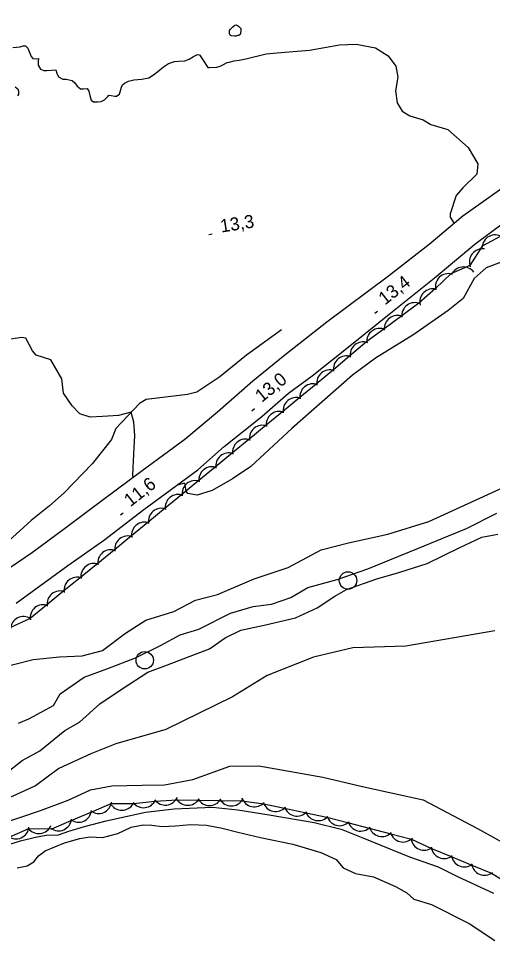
# Model space of a CAD drawing. Extents: x 643342 to 646936, y 5873857 to 5876103.
# Drawn here: x 645260 to 645368.8, y 5874232.4 to 5874444 of the extents above; entities that cross this region are included whole.
import ezdxf

# ---------------------------------------------------------------- set-up
doc = ezdxf.new("R2010")
doc.units = 0
for name, color, linetype in [('Niveau 1', 7, 'Continuous'), ('Niveau 2', 7, 'Continuous'), ('Niveau 21', 7, 'Continuous'), ('Niveau 22', 7, 'Continuous'), ('Niveau 3', 7, 'Continuous'), ('Niveau 36', 7, 'Continuous'), ('Niveau 4', 7, 'Continuous'), ('Niveau 44', 7, 'Continuous')]:
    doc.layers.add(name, color=color, linetype=linetype)

msp = doc.modelspace()

# ---------------------------------------------------------------- linework, layer by layer
at = {"layer": 'Niveau 1'}
msp.add_lwpolyline([(645242.67, 5874298.35), (645244.98, 5874297.7), (645249.37, 5874295.72), (645253.54, 5874295.31), (645258.53, 5874295.66), (645263.34, 5874296.94), (645269.42, 5874297.54), (645274.59, 5874297.73), (645279.29, 5874298.94), (645284.56, 5874302.93), (645289.25, 5874305.9), (645295.64, 5874307.93), (645300.65, 5874310.5), (645305.68, 5874311.85), (645314.06, 5874315.42), (645321.92, 5874318.02), (645329.45, 5874322.05), (645335.75, 5874323.66), (645344.8, 5874325.7), (645354.15, 5874328.58), (645372.21, 5874336.86)], dxfattribs=at)
at = {"layer": 'Niveau 2'}
for points in [[(645309.16, 5874442.08), (645309.61, 5874442.46), (645309.95, 5874442.53), (645310.25, 5874442.41), (645310.51, 5874442.24), (645311.04, 5874441.7), (645311.06, 5874441.36), (645310.98, 5874440.57), (645310.81, 5874440.32), (645310.58, 5874440.1), (645310.25, 5874440.08), (645309.92, 5874439.95), (645309.58, 5874439.93), (645308.8, 5874440.01), (645308.54, 5874440.18), (645308.42, 5874440.46), (645308.39, 5874440.8), (645308.45, 5874441.24), (645308.62, 5874441.5), (645309.16, 5874442.08)], [(645258.69, 5874437.32), (645260.38, 5874437.46), (645261.04, 5874437.71), (645261.62, 5874437.71), (645262.1, 5874437.16), (645262.89, 5874435.23)], [(645283.15, 5874426.65), (645283.65, 5874428.24), (645283.9, 5874428.8), (645284.3, 5874429.17), (645285.24, 5874429.59), (645286.48, 5874429.89), (645287.35, 5874429.96), (645288.27, 5874430.03), (645289.94, 5874430.36), (645291, 5874431.08), (645292.01, 5874431.79), (645293.24, 5874432.87), (645294.39, 5874433.64), (645295.76, 5874434.09), (645296.78, 5874434.17), (645298.18, 5874434.29), (645299.17, 5874434.66), (645300.19, 5874435.28), (645301.08, 5874435.69), (645301.52, 5874435.63), (645302.42, 5874434.24), (645303.46, 5874432.77), (645303.75, 5874432.74), (645305.5, 5874432.79), (645306.31, 5874433.05), (645306.92, 5874433.34), (645307.89, 5874433.9), (645308.37, 5874433.94), (645309.46, 5874434.27), (645310.67, 5874434.42), (645312.15, 5874434.74), (645316.83, 5874435.84), (645319.33, 5874436.14), (645322.14, 5874436.32), (645326.8, 5874436.75)], [(645326.8, 5874436.75), (645333.69, 5874437.93), (645337.5, 5874438.13), (645341.91, 5874437.27), (645344.82, 5874435.45), (645346.58, 5874433.03), (645347.07, 5874430.49), (645346.52, 5874427.36), (645346.91, 5874424.64), (645348.08, 5874422.74), (645349.83, 5874421.66), (645352.91, 5874420.74), (645354.61, 5874419.66), (645358.54, 5874418.5), (645363.17, 5874414.38), (645365.44, 5874410.65), (645365.2, 5874408.3), (645361.99, 5874405.1), (645360.42, 5874403.36), (645359.07, 5874399.18), (645359.07, 5874398.37), (645359.99, 5874396.98)], [(645262.89, 5874435.23), (645263.27, 5874434.82), (645264.15, 5874434.75), (645264.58, 5874434.78), (645264.49, 5874434.09), (645264.51, 5874433.27), (645265.07, 5874432.39), (645265.78, 5874432.06), (645266.46, 5874432.06), (645268.54, 5874432.18), (645268.8, 5874431.42), (645269.21, 5874430.58), (645270.13, 5874430.07), (645270.91, 5874430.04), (645272.34, 5874429.72), (645272.92, 5874429.23), (645273.42, 5874428.49), (645274.24, 5874427.87), (645274.93, 5874427.88), (645275.79, 5874427.95), (645276.14, 5874427.34), (645276.37, 5874426.29), (645276.7, 5874425.25), (645277.21, 5874424.9), (645278.19, 5874424.88), (645278.96, 5874424.94), (645279.75, 5874425.35), (645280.47, 5874426.09), (645280.69, 5874426.4), (645281.23, 5874426.35), (645282.12, 5874426.13), (645282.46, 5874426.15), (645282.78, 5874426.37), (645283.15, 5874426.65)], [(645259.84, 5874426.22), (645260.1, 5874426.63), (645260.05, 5874427.21), (645260.02, 5874427.6), (645259.19, 5874428.21)], [(645371.37, 5874388.34), (645367.35, 5874386.78), (645364.61, 5874384.31), (645362.06, 5874379.75), (645358.59, 5874377), (645350.76, 5874371.49), (645341.95, 5874366.02), (645336.63, 5874362.15), (645322.74, 5874349.9), (645313.32, 5874341.18), (645309.09, 5874338.38), (645304.44, 5874335.71), (645300.97, 5874334.6), (645298.85, 5874334.97), (645298.46, 5874335.53), (645298.17, 5874337.38), (645296.38, 5874336.92)], [(645286.29, 5874338.62), (645286.21, 5874339.12), (645286.33, 5874340.88), (645286.54, 5874345.45), (645286.7, 5874348.33), (645286.44, 5874351.35), (645285.86, 5874353.67), (645282.95, 5874352.88), (645279.3, 5874352.63), (645276.43, 5874352.48), (645274.1, 5874353.29), (645272.29, 5874355.09), (645270.35, 5874358.05), (645269.96, 5874361.3), (645267.45, 5874365.63), (645264.06, 5874366.71), (645263.2, 5874367.76), (645261.67, 5874370.64), (645260.79, 5874370.81), (645256.72, 5874370.18)], [(645260.02, 5874282.28), (645262.36, 5874283.26), (645267.99, 5874286.35), (645269.56, 5874289.04), (645275.08, 5874292.83), (645280.49, 5874294.85), (645286.86, 5874297.29), (645292.62, 5874300.1), (645297.12, 5874302.58), (645301.41, 5874303.88), (645308.63, 5874307.55), (645313.89, 5874309.09), (645318.05, 5874309.62), (645322.5, 5874311.1), (645326.37, 5874313.42), (645333.13, 5874315.24), (645340.19, 5874317.73), (645345.24, 5874319.78), (645351.82, 5874322.47), (645358.68, 5874325.29), (645362.82, 5874326.93), (645369.8, 5874330.52)], [(645289.68, 5874294.04), (645294.18, 5874295.7), (645300.39, 5874298.08), (645303.81, 5874299.37), (645307.44, 5874301.86), (645311.06, 5874303.64), (645316.35, 5874304.77), (645323.6, 5874306.45), (645328.58, 5874308.74), (645332.61, 5874311.43), (645335.25, 5874312.96), (645342.26, 5874315.45), (645347.3, 5874316.86), (645353.76, 5874318.95), (645361.16, 5874322.52), (645366.36, 5874325), (645370.05, 5874325.67)], [(645369.34, 5874303.51), (645348.89, 5874299.96), (645336.76, 5874299.58), (645327.67, 5874297.41), (645317.07, 5874293.26), (645309.1, 5874288.35), (645293.81, 5874280.81), (645282.32, 5874277.53), (645276.62, 5874275.25), (645269.24, 5874271.91), (645263.89, 5874267.89), (645253.43, 5874263.15), (645241.62, 5874259.5), (645234.18, 5874256.85), (645222.41, 5874252.49), (645212.69, 5874250.51), (645204.39, 5874248.52), (645199.45, 5874246.11)], [(645211.19, 5874263.91), (645214.93, 5874261.36), (645218.67, 5874260.57), (645226.45, 5874261.47), (645233.78, 5874262.11), (645241.81, 5874264.43), (645247.71, 5874265.44), (645255.38, 5874269.5), (645260.83, 5874273.76), (645264.89, 5874275.92), (645270.65, 5874280.61), (645273.97, 5874282.55), (645278.66, 5874286.75), (645283.8, 5874290.16), (645289.68, 5874294.04)], [(645255.49, 5874259.08), (645265.02, 5874262.23), (645271.36, 5874264.62), (645276.54, 5874266.99), (645281.4, 5874267.92), (645288.36, 5874268.06), (645293.51, 5874268.19), (645299.99, 5874269.41), (645308.52, 5874272.42), (645315.19, 5874272.54), (645320.35, 5874271.61), (645329.83, 5874269.93), (645339.28, 5874267.71), (645352.89, 5874264.68), (645365.37, 5874258.15), (645379.58, 5874250.23)]]:
    msp.add_lwpolyline(points, dxfattribs=at)
at = {"layer": 'Niveau 21'}
for points in [[(645427.34, 5874449.1), (645419.04, 5874441.54), (645411.21, 5874435.52), (645403.96, 5874429.66), (645395.89, 5874423.74), (645387.7, 5874417.92), (645378.63, 5874411.46), (645370.38, 5874404.59), (645361.96, 5874398.64), (645354.27, 5874392.16), (645344.89, 5874384.85), (645330.74, 5874374.3), (645321.14, 5874366.74)], [(645259.47, 5874309.83), (645271.35, 5874318.5), (645279.47, 5874324.21), (645288.77, 5874331.3), (645301.18, 5874340.46), (645307.22, 5874345.79), (645315.83, 5874352.7), (645321.98, 5874358.03), (645327.41, 5874362.03), (645336.45, 5874369.2), (645345.82, 5874376.74), (645355.41, 5874384.41), (645364.76, 5874392.18), (645371.61, 5874397.32), (645380.03, 5874403.27), (645390.78, 5874410.67), (645400.91, 5874416.97), (645408.76, 5874422.64), (645416.9, 5874429.14), (645428.32, 5874438.44), (645437.55, 5874447.7)], [(645321.14, 5874366.74), (645313.75, 5874360.74), (645305.63, 5874353.63), (645298.14, 5874347.39), (645288.39, 5874340.16), (645279.41, 5874333.57), (645270.54, 5874326.87), (645263.22, 5874321.44), (645254.75, 5874315.7)]]:
    msp.add_lwpolyline(points, dxfattribs=at)
at = {"layer": 'Niveau 22'}
msp.add_lwpolyline([(645251.93, 5874252.74), (645260.44, 5874255.34), (645263.91, 5874256.18), (645266.34, 5874256.59), (645269.16, 5874256.67), (645271.56, 5874257.54), (645275.13, 5874258.62), (645280.09, 5874259.91), (645289.11, 5874261.85), (645295.74, 5874262.67), (645304.52, 5874263.05), (645310.31, 5874262.4), (645317.54, 5874261.27), (645327.85, 5874259.52), (645334.05, 5874257.96), (645338.63, 5874256.17), (645349.71, 5874251.65), (645356.31, 5874249.3), (645360.78, 5874247.14), (645369.01, 5874243.26)], dxfattribs=at)
at = {"layer": 'Niveau 3'}
for p, q in [((645303.68, 5874394.45), (645304.48, 5874394.58)), ((645341.8, 5874376.36), (645342.43, 5874376.86)), ((645313.55, 5874353.98), (645314.17, 5874354.48)), ((645283.37, 5874330.08), (645284, 5874330.57))]:
    msp.add_line(p, q, dxfattribs=at)
at = {"layer": 'Niveau 36'}
for centre in [(645335.63, 5874315.03), (645288.97, 5874296.73)]:
    msp.add_circle(centre, 2, dxfattribs=at)
at = {"layer": 'Niveau 4'}
for points in [[(645320.33, 5874372.54), (645312.36, 5874366.73), (645306.18, 5874361.74), (645300.96, 5874358.23), (645298.78, 5874357.72), (645289.32, 5874356.6), (645287.75, 5874355.67), (645282.32, 5874349.91), (645281.33, 5874347.39), (645276.93, 5874341.82), (645270.5, 5874335.17), (645267.1, 5874332.13), (645262.9, 5874328.79), (645257.74, 5874324.1)], [(645259.69, 5874249.14), (645262.01, 5874249.54), (645263.48, 5874250.47), (645264.56, 5874251.84), (645266.13, 5874253.01), (645270.58, 5874254.86), (645274.04, 5874255.81), (645276.36, 5874256.21), (645279.3, 5874256.06), (645282.76, 5874257.01), (645285.84, 5874258.41), (645288.62, 5874258.96), (645290.62, 5874258.87), (645292.98, 5874258.56), (645296.02, 5874258.78), (645299.52, 5874259.02), (645303.17, 5874258.93), (645306.73, 5874258.24), (645310.31, 5874257.31), (645315.56, 5874256.04), (645322.93, 5874254.56), (645329.39, 5874252.66), (645332.9, 5874251.02), (645334.55, 5874249.14)], [(645334.55, 5874249.14), (645337.33, 5874247.81), (645341.49, 5874247.04), (645346.56, 5874244.81), (645349.11, 5874243.34), (645350.73, 5874241.93), (645354.8, 5874240.69), (645363.4, 5874236.36), (645369.29, 5874232.42)]]:
    msp.add_lwpolyline(points, dxfattribs=at)
at = {"layer": 'Niveau 44'}
for points in [[(645370.71, 5874394.03), (645366.43, 5874391.75), (645363.59, 5874387.33), (645359.19, 5874385.41), (645355.71, 5874382.02), (645351.87, 5874378.66), (645347.97, 5874375.78), (645343.82, 5874372.74), (645339.91, 5874369.86), (645336, 5874366.48), (645332.28, 5874363.37), (645328.33, 5874360.07), (645324.58, 5874356.99), (645320.6, 5874353.73), (645316.85, 5874350.65), (645312.87, 5874347.38), (645309.12, 5874344.3), (645305.14, 5874341.03), (645301.4, 5874337.95), (645297.42, 5874334.68), (645293.67, 5874331.6), (645289.7, 5874328.33), (645285.95, 5874325.25), (645281.96, 5874322), (645278.19, 5874318.94), (645274.2, 5874315.69), (645270.43, 5874312.63), (645266.44, 5874309.38), (645262.68, 5874306.32), (645258.04, 5874304.18)], [(645257.88, 5874256.18), (645262.34, 5874258.11), (645267.65, 5874258.02), (645272.11, 5874259.94), (645276.83, 5874261.98), (645281.29, 5874263.9), (645286.49, 5874263.87), (645291.31, 5874264.44), (645296.4, 5874264.73), (645301.26, 5874264.66), (645306.4, 5874264.58), (645311.25, 5874264.51), (645316.28, 5874263.83)], [(645316.28, 5874263.83), (645321.02, 5874262.81), (645326.05, 5874261.72), (645330.8, 5874260.7), (645335.78, 5874259.43), (645340.48, 5874258.22), (645345.46, 5874256.93), (645350.16, 5874255.72), (645354.8, 5874253.53), (645359.29, 5874251.69), (645364.05, 5874249.72), (645368.54, 5874247.87), (645372.87, 5874245.28)]]:
    msp.add_lwpolyline(points, dxfattribs=at)
for centre, start, end in [((645369.4, 5874391.34), 58.0426, 178.0205), ((645369.4, 5874391.34), 58.0426, 178.0205), ((645369.4, 5874391.34), 58.0426, 178.0205), ((645366.48, 5874388.13), 81.4811, 201.4591), ((645366.48, 5874388.13), 81.4811, 201.4591), ((645366.48, 5874388.13), 81.4811, 201.4591), ((645362.11, 5874383.97), 36.2892, 156.2672), ((645362.11, 5874383.97), 36.2892, 156.2672), ((645362.11, 5874383.97), 36.2892, 156.2672), ((645358.68, 5874382.45), 74.3166, 194.2945), ((645358.68, 5874382.45), 74.3166, 194.2945), ((645358.68, 5874382.45), 74.3166, 194.2945), ((645355.1, 5874378.96), 74.3166, 194.2945), ((645355.1, 5874378.96), 74.3166, 194.2945), ((645355.1, 5874378.96), 74.3166, 194.2945), ((645350.97, 5874375.8), 66.364, 186.3419), ((645350.97, 5874375.8), 66.364, 186.3419), ((645350.97, 5874375.8), 66.364, 186.3419), ((645346.94, 5874372.84), 66.364, 186.3419), ((645346.94, 5874372.84), 66.364, 186.3419), ((645346.94, 5874372.84), 66.364, 186.3419), ((645342.91, 5874369.88), 66.364, 186.3419), ((645342.91, 5874369.88), 66.364, 186.3419), ((645342.91, 5874369.88), 66.364, 186.3419), ((645339.11, 5874366.78), 69.9831, 189.9611), ((645339.11, 5874366.78), 69.9831, 189.9611), ((645339.11, 5874366.78), 69.9831, 189.9611), ((645335.27, 5874363.57), 69.9831, 189.9611), ((645335.27, 5874363.57), 69.9831, 189.9611), ((645335.27, 5874363.57), 69.9831, 189.9611), ((645331.44, 5874360.36), 69.9831, 189.9611), ((645331.44, 5874360.36), 69.9831, 189.9611), ((645331.44, 5874360.36), 69.9831, 189.9611), ((645327.57, 5874357.17), 69.3978, 189.3758), ((645327.57, 5874357.17), 69.3978, 189.3758), ((645327.57, 5874357.17), 69.3978, 189.3758), ((645323.71, 5874354), 69.3978, 189.3758), ((645323.71, 5874354), 69.3978, 189.3758), ((645323.71, 5874354), 69.3978, 189.3758), ((645319.84, 5874350.83), 69.3978, 189.3758), ((645319.84, 5874350.83), 69.3978, 189.3758), ((645319.84, 5874350.83), 69.3978, 189.3758), ((645315.98, 5874347.65), 69.3978, 189.3758), ((645315.98, 5874347.65), 69.3978, 189.3758), ((645315.98, 5874347.65), 69.3978, 189.3758), ((645312.12, 5874344.48), 69.45, 189.4279), ((645312.12, 5874344.48), 69.45, 189.4279), ((645312.12, 5874344.48), 69.45, 189.4279), ((645308.25, 5874341.31), 69.45, 189.4279), ((645308.25, 5874341.31), 69.45, 189.4279), ((645308.25, 5874341.31), 69.45, 189.4279), ((645304.39, 5874338.13), 69.45, 189.4279), ((645304.39, 5874338.13), 69.45, 189.4279), ((645304.39, 5874338.13), 69.45, 189.4279), ((645300.53, 5874334.95), 69.45, 189.4279), ((645300.53, 5874334.95), 69.45, 189.4279), ((645300.53, 5874334.95), 69.45, 189.4279), ((645296.67, 5874331.78), 69.45, 189.4279), ((645296.67, 5874331.78), 69.45, 189.4279), ((645296.67, 5874331.78), 69.45, 189.4279), ((645292.8, 5874328.6), 69.45, 189.4279), ((645292.8, 5874328.6), 69.45, 189.4279), ((645292.8, 5874328.6), 69.45, 189.4279), ((645288.94, 5874325.43), 69.45, 189.4279), ((645288.94, 5874325.43), 69.45, 189.4279), ((645288.94, 5874325.43), 69.45, 189.4279), ((645285.07, 5874322.26), 69.154, 189.1319), ((645285.07, 5874322.26), 69.154, 189.1319), ((645285.07, 5874322.26), 69.154, 189.1319), ((645281.19, 5874319.1), 69.154, 189.1319), ((645281.19, 5874319.1), 69.154, 189.1319), ((645281.19, 5874319.1), 69.154, 189.1319), ((645277.31, 5874315.95), 69.154, 189.1319), ((645277.31, 5874315.95), 69.154, 189.1319), ((645277.31, 5874315.95), 69.154, 189.1319), ((645273.43, 5874312.79), 69.154, 189.1319), ((645273.43, 5874312.79), 69.154, 189.1319), ((645273.43, 5874312.79), 69.154, 189.1319), ((645269.55, 5874309.64), 69.154, 189.1319), ((645269.55, 5874309.64), 69.154, 189.1319), ((645269.55, 5874309.64), 69.154, 189.1319), ((645265.67, 5874306.48), 69.154, 189.1319), ((645265.67, 5874306.48), 69.154, 189.1319), ((645265.67, 5874306.48), 69.154, 189.1319), ((645261.13, 5874303.75), 56.6104, 176.5883), ((645261.13, 5874303.75), 56.6104, 176.5883), ((645261.13, 5874303.75), 56.6104, 176.5883), ((645293.66, 5874266.5), 216.7617, 336.7396), ((645293.66, 5874266.5), 216.7617, 336.7396), ((645293.66, 5874266.5), 216.7617, 336.7396), ((645314.14, 5874266.1), 197.8423, 317.8203), ((645314.14, 5874266.1), 197.8423, 317.8203), ((645314.14, 5874266.1), 197.8423, 317.8203), ((645278.36, 5874264.56), 233.338, 353.3159), ((645278.36, 5874264.56), 233.338, 353.3159), ((645278.36, 5874264.56), 233.338, 353.3159), ((645283.73, 5874265.32), 216.7617, 336.7396), ((645283.73, 5874265.32), 216.7617, 336.7396), ((645283.73, 5874265.32), 216.7617, 336.7396), ((645288.69, 5874265.91), 216.7617, 336.7396), ((645288.69, 5874265.91), 216.7617, 336.7396), ((645288.69, 5874265.91), 216.7617, 336.7396), ((645298.85, 5874266.46), 209.164, 329.142), ((645298.85, 5874266.46), 209.164, 329.142), ((645298.85, 5874266.46), 209.164, 329.142), ((645303.85, 5874266.39), 209.164, 329.142), ((645303.85, 5874266.39), 209.164, 329.142), ((645303.85, 5874266.39), 209.164, 329.142), ((645308.85, 5874266.31), 209.164, 329.142), ((645308.85, 5874266.31), 209.164, 329.142), ((645308.85, 5874266.31), 209.164, 329.142), ((645319.02, 5874265.04), 197.8423, 317.8203), ((645319.02, 5874265.04), 197.8423, 317.8203), ((645319.02, 5874265.04), 197.8423, 317.8203), ((645323.91, 5874263.99), 197.8423, 317.8203), ((645323.91, 5874263.99), 197.8423, 317.8203), ((645323.91, 5874263.99), 197.8423, 317.8203), ((645273.77, 5874262.58), 233.338, 353.3159), ((645273.77, 5874262.58), 233.338, 353.3159), ((645273.77, 5874262.58), 233.338, 353.3159), ((645328.8, 5874262.93), 197.8423, 317.8203), ((645328.8, 5874262.93), 197.8423, 317.8203), ((645328.8, 5874262.93), 197.8423, 317.8203), ((645333.72, 5874261.78), 195.5388, 315.5167), ((645333.72, 5874261.78), 195.5388, 315.5167), ((645333.72, 5874261.78), 195.5388, 315.5167), ((645264.65, 5874259.95), 217.4435, 337.4215), ((645264.65, 5874259.95), 217.4435, 337.4215), ((645264.65, 5874259.95), 217.4435, 337.4215), ((645269.18, 5874260.6), 233.338, 353.3159), ((645269.18, 5874260.6), 233.338, 353.3159), ((645269.18, 5874260.6), 233.338, 353.3159), ((645338.57, 5874260.53), 195.5388, 315.5167), ((645338.57, 5874260.53), 195.5388, 315.5167), ((645338.57, 5874260.53), 195.5388, 315.5167), ((645259.41, 5874258.76), 233.3964, 353.3743), ((645259.41, 5874258.76), 233.3964, 353.3743), ((645259.41, 5874258.76), 233.3964, 353.3743), ((645343.41, 5874259.28), 195.5388, 315.5167), ((645343.41, 5874259.28), 195.5388, 315.5167), ((645343.41, 5874259.28), 195.5388, 315.5167), ((645348.25, 5874258.03), 195.5388, 315.5167), ((645348.25, 5874258.03), 195.5388, 315.5167), ((645348.25, 5874258.03), 195.5388, 315.5167), ((645353.1, 5874256.15), 187.6143, 307.5923), ((645353.1, 5874256.15), 187.6143, 307.5923), ((645353.1, 5874256.15), 187.6143, 307.5923), ((645357.72, 5874254.24), 187.6143, 307.5923), ((645357.72, 5874254.24), 187.6143, 307.5923), ((645357.72, 5874254.24), 187.6143, 307.5923), ((645362.34, 5874252.33), 187.6143, 307.5923), ((645362.34, 5874252.33), 187.6143, 307.5923), ((645362.34, 5874252.33), 187.6143, 307.5923), ((645366.96, 5874250.43), 187.6143, 307.5923), ((645366.96, 5874250.43), 187.6143, 307.5923), ((645366.96, 5874250.43), 187.6143, 307.5923)]:
    msp.add_arc(centre, 3, start, end, dxfattribs=at)

# ---------------------------------------------------------------- texts
at = {"layer": 'Niveau 3'}
for s, rotation, p in [('13,3 ', 8.941, (645306.54, 5874394.86)), ('13,4 ', 38.1291, (645344.09, 5874378.11)), ('13,0 ', 39.047, (645315.81, 5874355.76)), ('11,6 ', 37.9146, (645285.67, 5874331.82))]:
    msp.add_text(s, height=3, rotation=rotation, dxfattribs=at).set_placement(p)

doc.saveas('drawing.dxf')
